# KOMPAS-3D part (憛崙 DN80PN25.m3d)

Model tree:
1. Объединить компоненты:1  (labels: СЕНС DN80PN25)

Referenced files in D:\Савин\!СЕНСОР\3D для заказчика\!Новый перечень\СЕНС\1. СЕНС\DN80\: СЕНС DN80PN25.a3d
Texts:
  СЕНС DN80PN25
  ООО НПП Сенсор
